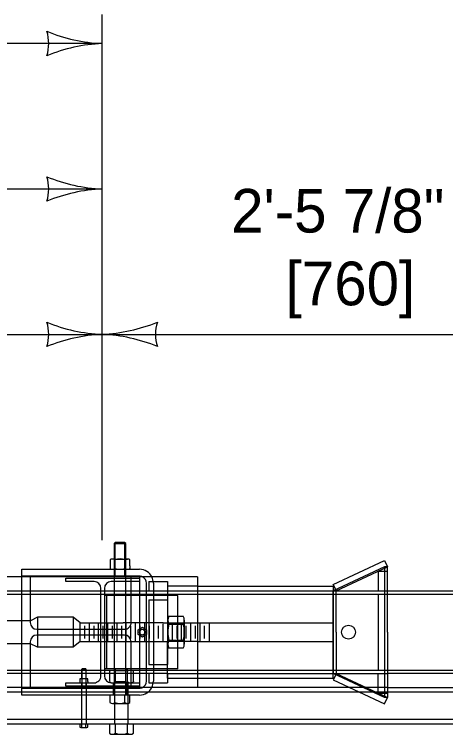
# Model space of a CAD drawing. Extents: x 49991.4 to 50021, y 49987.6 to 50011.4.
# Drawn here: x 50015.632 to 50016.226, y 49997.392 to 49998.382 of the extents above; entities that cross this region are included whole.
import ezdxf

# ---------------------------------------------------------------- set-up
doc = ezdxf.new("R2010")
doc.units = 0
for name, color, linetype in [('Level 1', 7, 'Continuous'), ('Level 2', 7, 'Continuous'), ('Level 3', 7, 'Continuous'), ('Level 4', 7, 'Continuous')]:
    doc.layers.add(name, color=color, linetype=linetype)

msp = doc.modelspace()

# ---------------------------------------------------------------- linework, layer by layer
at = {"layer": 'Level 1'}
for p, q in [((50015.76969, 49997.65453), (50015.77128, 49997.65611)), ((50015.76969, 49997.65453), (50015.77128, 49997.65611)), ((50015.78398, 49997.65611), (50015.77128, 49997.65611)), ((50015.78398, 49997.65611), (50015.77128, 49997.65611)), ((50015.78556, 49997.65453), (50015.78398, 49997.65611)), ((50015.78556, 49997.65453), (50015.78398, 49997.65611)), ((50015.76969, 49997.65453), (50015.76969, 49997.63336)), ((50015.78556, 49997.63336), (50015.78556, 49997.65453)), ((50015.76398, 49997.63241), (50015.76398, 49997.62335)), ((50015.77014, 49997.63336), (50015.76741, 49997.63336)), ((50015.77014, 49997.63336), (50015.78802, 49997.63336)), ((50015.77085, 49997.62014), (50015.77085, 49997.63241)), ((50015.78459, 49997.62014), (50015.78459, 49997.63241)), ((50015.79146, 49997.62411), (50015.79146, 49997.63241)), ((50016.07143, 49997.5983), (50016.14204, 49997.63113)), ((50016.14204, 49997.63113), (50016.14606, 49997.62253)), ((50015.76398, 49997.62335), (50015.76398, 49997.62014)), ((50015.76741, 49997.61919), (50015.78802, 49997.61919)), ((50015.79146, 49997.62411), (50015.79146, 49997.62014)), ((50015.79626, 49997.61919), (50015.8046, 49997.61919)), ((50016.14204, 49997.62253), (50016.07143, 49997.58969)), ((50016.14606, 49997.62253), (50016.14204, 49997.62253)), ((50016.14204, 49997.62253), (50016.14204, 49997.44294)), ((50016.14606, 49997.53273), (50016.14606, 49997.62253)), ((50016.14606, 49997.53273), (50016.14606, 49997.61662)), ((50015.88463, 49997.60868), (50012.22863, 49997.60868)), ((50015.64262, 49997.60969), (50015.64262, 49997.60868)), ((50015.65417, 49997.60868), (50015.65417, 49997.60969)), ((50015.8046, 49997.60969), (50015.79626, 49997.60969)), ((50015.8046, 49997.60969), (50015.8046, 49997.60868)), ((50015.88463, 49997.60868), (50015.88463, 49997.45678)), ((50015.88463, 49997.59602), (50016.07143, 49997.59602)), ((50016.07473, 49997.59123), (50016.07143, 49997.5983)), ((50016.07143, 49997.59602), (50016.07143, 49997.54539)), ((50016.07143, 49997.58969), (50016.07143, 49997.47577)), ((50016.07143, 49997.47577), (50016.07143, 49997.58969)), ((50016.07473, 49997.59123), (50016.07545, 49997.58969)), ((50016.14606, 49997.58972), (50016.35107, 49997.58969)), ((50015.88463, 49997.54539), (50016.07143, 49997.54539)), ((50016.14606, 49997.53273), (50016.14606, 49997.44294)), ((50016.14606, 49997.53273), (50016.14606, 49997.44884)), ((50015.88463, 49997.52007), (50016.07143, 49997.52007)), ((50016.07143, 49997.46944), (50016.07143, 49997.52007)), ((50015.88463, 49997.46944), (50016.07143, 49997.46944)), ((50016.14204, 49997.44294), (50016.07143, 49997.47577)), ((50016.07473, 49997.47423), (50016.07143, 49997.46717)), ((50016.07143, 49997.46717), (50016.14204, 49997.43433)), ((50016.34628, 49997.47577), (50016.14606, 49997.47574)), ((50015.88463, 49997.45678), (50012.22863, 49997.45678)), ((50016.09376, 49997.45678), (50015.40225, 49997.45678)), ((50015.64262, 49997.45678), (50015.64262, 49997.45577)), ((50015.65417, 49997.45678), (50015.65417, 49997.45577)), ((50016.14606, 49997.45678), (50016.34164, 49997.45678)), ((50016.14204, 49997.43433), (50016.14606, 49997.44294)), ((50016.14606, 49997.44294), (50016.14204, 49997.44294)), ((50016.34164, 49997.40615), (50015.40225, 49997.40615)), ((50015.72387, 49997.40154), (50015.73212, 49997.40154)), ((50015.72387, 49997.40154), (50015.73212, 49997.40154)), ((50015.72524, 49997.40198), (50015.72524, 49997.40615)), ((50015.72524, 49997.40198), (50015.72524, 49997.40615)), ((50015.73074, 49997.40198), (50015.73074, 49997.40615)), ((50015.73074, 49997.40198), (50015.73074, 49997.40615)), ((50015.77141, 49997.39365), (50015.77141, 49997.40615)), ((50015.77141, 49997.39365), (50015.77141, 49997.40615)), ((50015.7879, 49997.39365), (50015.7879, 49997.40615)), ((50015.7879, 49997.39365), (50015.7879, 49997.40615)), ((50015.76729, 49997.39233), (50015.79203, 49997.39233)), ((50015.76729, 49997.39233), (50015.79203, 49997.39233))]:
    msp.add_line(p, q, dxfattribs=at)
for points in [[(50015.8046, 49997.60969), (50015.64262, 49997.60969), (50015.64262, 49997.61919), (50015.8046, 49997.61919)], [(50015.73349, 49997.40198), (50015.73349, 49997.40615), (50015.7225, 49997.40615), (50015.7225, 49997.40198)], [(50015.73349, 49997.40198), (50015.73349, 49997.40615), (50015.7225, 49997.40615), (50015.7225, 49997.40198)], [(50015.79615, 49997.39365), (50015.79615, 49997.40615), (50015.76317, 49997.40615), (50015.76317, 49997.39365)], [(50015.79615, 49997.39365), (50015.79615, 49997.40615), (50015.76317, 49997.40615), (50015.76317, 49997.39365)]]:
    msp.add_lwpolyline(points, dxfattribs=at)
msp.add_lwpolyline([(50015.80847, 49997.53958), (50015.81442, 49997.53616), (50015.81442, 49997.52931), (50015.80847, 49997.52588), (50015.80252, 49997.52931), (50015.80252, 49997.53616)], close=True, dxfattribs=at)
for centre, major_axis, start_param, end_param in [((50015.76741, 49997.62671), (-0.00667, 0), 4.291765, 5.25309), ((50015.76741, 49997.62671), (-0.00667, 0), 4.171688, 4.291765), ((50015.77772, 49997.60817), (-0.02527, 0), 4.437007, 4.987771), ((50015.78803, 49997.62671), (-0.00667, 0), 4.538561, 5.25309), ((50015.78803, 49997.62671), (-0.00667, 0), 4.171687, 4.538561), ((50015.76741, 49997.62584), (-0.00667, 0), 1.030095, 2.111498), ((50015.77772, 49997.64438), (-0.02527, 0), 1.295415, 1.84618), ((50015.78803, 49997.62584), (-0.00667, 0), 1.030095, 2.111498), ((50015.8046, 49997.6002), (-0.01904, 0), 3.604629, 4.712389), ((50015.8046, 49997.6002), (-0.00952, 0), 4.246301, 4.712389), ((50015.80847, 49997.53273), (-0.00353, 0), 5.020149, 5.195336), ((50015.80847, 49997.53273), (-0.00353, 0), 5.020149, 5.195336), ((50015.80847, 49997.53273), (-0.00353, 0), 4.455169, 4.688481), ((50015.80847, 49997.53273), (-0.00353, 0), 4.455169, 4.688481), ((50015.80847, 49997.53273), (-0.00353, 0), 4.455169, 4.688481), ((50015.80847, 49997.53273), (-0.00353, 0), 4.455169, 4.688481), ((50015.80847, 49997.53273), (-0.00353, 0), 0.050953, 0.393038), ((50015.80847, 49997.53273), (-0.00353, 0), 0.050953, 0.393038), ((50015.80847, 49997.53273), (-0.00353, 0), 5.563044, 5.953877), ((50015.80847, 49997.53273), (-0.00353, 0), 5.563044, 5.953877), ((50015.80847, 49997.53273), (-0.00353, 0), 0.642388, 1.07769), ((50015.80847, 49997.53273), (-0.00353, 0), 0.642388, 1.07769), ((50015.80847, 49997.53273), (-0.00353, 0), 1.524027, 1.964776), ((50015.80847, 49997.53273), (-0.00353, 0), 3.688317, 4.066094), ((50015.80847, 49997.53273), (-0.00353, 0), 3.688317, 4.066094), ((50015.80847, 49997.53273), (-0.00353, 0), 3.688317, 4.066094), ((50015.80847, 49997.53273), (-0.00353, 0), 3.688317, 4.066094), ((50015.80847, 49997.53273), (-0.00353, 0), 2.328597, 2.659517), ((50015.80847, 49997.53273), (-0.00353, 0), 2.328597, 2.659517), ((50015.80847, 49997.53273), (-0.00353, 0), 2.328597, 2.659517), ((50015.80847, 49997.53273), (-0.00353, 0), 2.328597, 2.659517), ((50015.80847, 49997.53273), (-0.00353, 0), 3.003616, 3.367487), ((50015.80847, 49997.53273), (-0.00353, 0), 3.003616, 3.367487), ((50015.80847, 49997.53273), (-0.00353, 0), 3.003616, 3.367487), ((50015.80847, 49997.53273), (-0.00353, 0), 3.003616, 3.367487), ((50015.72387, 49997.40388), (-0.00235, 0), 0.945365, 2.196228), ((50015.72387, 49997.40388), (-0.00235, 0), 0.945365, 2.196228), ((50015.72799, 49997.41024), (-0.00872, 0), 1.250246, 1.891347), ((50015.72799, 49997.41024), (-0.00872, 0), 1.250246, 1.891347), ((50015.73212, 49997.40388), (-0.00235, 0), 0.945366, 2.196226), ((50015.73212, 49997.40388), (-0.00235, 0), 0.945366, 2.196226), ((50015.76729, 49997.39935), (-0.00704, 0), 0.945365, 2.196228), ((50015.76729, 49997.39935), (-0.00704, 0), 0.945365, 2.196228), ((50015.77966, 49997.41842), (-0.02617, 0), 1.250246, 1.891347), ((50015.77966, 49997.41842), (-0.02617, 0), 1.250246, 1.891347), ((50015.79203, 49997.39935), (-0.00704, 0), 0.945366, 2.196226), ((50015.79203, 49997.39935), (-0.00704, 0), 0.945366, 2.196226)]:
    msp.add_ellipse(centre, major_axis=major_axis, ratio=0.99715, start_param=start_param, end_param=end_param, dxfattribs=at)
msp.add_ellipse((50015.80847, 49997.53273), major_axis=(-0.00397, 0), ratio=0.99715, dxfattribs=at)
msp.add_ellipse((50015.80847, 49997.53273), major_axis=(-0.00397, 0), ratio=0.99715, dxfattribs=at)
at = {"layer": 'Level 3'}
for p, q in [((50015.7531, 49997.65919), (50015.7531, 49998.3823)), ((50015.7531, 49998.34228), (50001.2124, 49998.34228)), ((50012.22863, 49998.14228), (50015.7531, 49998.14228)), ((50013.1585, 49997.94228), (50015.7531, 49997.94228)), ((50015.7531, 49997.94228), (50016.49863, 49997.94228))]:
    msp.add_line(p, q, dxfattribs=at)
for centre, radius, start, end in [((50015.76226, 49998.56441), 0.22232, 247.45601, 267.63952), ((50015.62489, 49998.34228), 0.05477, 342.13882, 17.86118), ((50015.76459, 49998.10957), 0.233, 92.82731, 112.07716), ((50015.76226, 49998.36441), 0.22232, 247.45601, 267.63952), ((50015.62489, 49998.14228), 0.05477, 342.13882, 17.86118), ((50015.76459, 49997.90957), 0.233, 92.82731, 112.07716), ((50015.76226, 49998.16441), 0.22232, 247.45601, 267.63952), ((50015.62489, 49997.94228), 0.05477, 342.13882, 17.86118), ((50015.74161, 49998.17499), 0.233, 272.82731, 292.07716), ((50015.88131, 49997.94228), 0.05477, 162.13882, 197.86118), ((50015.76459, 49997.70957), 0.233, 92.82731, 112.07716), ((50015.74394, 49997.72015), 0.22232, 67.45601, 87.63952)]:
    msp.add_arc(centre, radius, start, end, dxfattribs=at)
at = {"layer": 'Level 4'}
for p, q in [((50015.76969, 49997.65453), (50015.78556, 49997.65453)), ((50015.76969, 49997.65453), (50015.78556, 49997.65453)), ((50015.77128, 49997.60864), (50015.77128, 49997.65453)), ((50015.78398, 49997.65453), (50015.78398, 49997.60864)), ((50015.76969, 49997.63336), (50015.76969, 49997.44627)), ((50015.78556, 49997.44627), (50015.78556, 49997.63336)), ((50016.07545, 49997.58969), (50016.14606, 49997.62253)), ((50016.13337, 49997.61662), (50016.14606, 49997.61662)), ((50016.13337, 49997.61662), (50016.13337, 49997.58972)), ((50015.81412, 49997.46526), (50015.81412, 49997.6002)), ((50015.81754, 49997.60235), (50015.81754, 49997.58969)), ((50015.81754, 49997.60235), (50015.84293, 49997.60235)), ((50015.82365, 49997.6002), (50015.82365, 49997.46526)), ((50015.84293, 49997.60235), (50015.84293, 49997.58969)), ((50015.88463, 49997.59602), (50015.84293, 49997.59602)), ((50015.84293, 49997.59602), (50015.84293, 49997.54539)), ((50015.31803, 49997.58969), (50015.84293, 49997.58969)), ((50015.75144, 49997.4726), (50015.75144, 49997.59286)), ((50015.7562, 49997.59286), (50015.7562, 49997.4726)), ((50015.84293, 49997.58969), (50016.07143, 49997.58969)), ((50016.07143, 49997.58969), (50016.14606, 49997.58969)), ((50016.07545, 49997.53273), (50016.07545, 49997.58969)), ((50015.27995, 49997.58495), (50016.34934, 49997.58495)), ((50015.85754, 49997.58336), (50015.7562, 49997.58336)), ((50015.7594, 49997.4821), (50015.7594, 49997.58336)), ((50015.81754, 49997.57703), (50015.84293, 49997.57703)), ((50015.81754, 49997.57703), (50015.81754, 49997.48843)), ((50015.84293, 49997.57703), (50015.84293, 49997.48843)), ((50015.85754, 49997.4821), (50015.85754, 49997.58336)), ((50016.13337, 49997.58495), (50016.13337, 49997.48052)), ((50015.65468, 49997.54855), (50015.52139, 49997.54855)), ((50015.6642, 49997.5533), (50015.65468, 49997.54855)), ((50015.71339, 49997.5533), (50015.6642, 49997.5533)), ((50015.6642, 49997.5533), (50015.6642, 49997.51216)), ((50015.72291, 49997.54539), (50015.71339, 49997.5533)), ((50015.71339, 49997.5533), (50015.71339, 49997.51216)), ((50015.84351, 49997.51643), (50015.84351, 49997.54932)), ((50015.84503, 49997.5548), (50015.86473, 49997.5548)), ((50015.86626, 49997.54932), (50015.86626, 49997.51643)), ((50015.66325, 49997.53678), (50015.78398, 49997.53678)), ((50015.72291, 49997.54539), (50015.78209, 49997.54539)), ((50015.72291, 49997.52007), (50015.72291, 49997.54539)), ((50015.72926, 49997.52387), (50015.72926, 49997.54159)), ((50015.73561, 49997.52007), (50015.73561, 49997.54539)), ((50015.74195, 49997.52387), (50015.74195, 49997.54159)), ((50015.7483, 49997.52007), (50015.7483, 49997.54539)), ((50015.75465, 49997.52387), (50015.75465, 49997.54159)), ((50015.761, 49997.52007), (50015.761, 49997.54539)), ((50015.76734, 49997.52387), (50015.76734, 49997.54159)), ((50015.77369, 49997.52007), (50015.77369, 49997.54539)), ((50015.78004, 49997.52387), (50015.78004, 49997.54159)), ((50015.83716, 49997.54539), (50015.78209, 49997.54539)), ((50015.78638, 49997.53905), (50015.78638, 49997.54539)), ((50015.78638, 49997.52007), (50015.78638, 49997.53905)), ((50015.79273, 49997.52968), (50015.79273, 49997.54159)), ((50015.79908, 49997.52007), (50015.79908, 49997.54539)), ((50015.80543, 49997.52387), (50015.80543, 49997.54159)), ((50015.81177, 49997.52007), (50015.81177, 49997.54539)), ((50015.81812, 49997.52387), (50015.81812, 49997.54159)), ((50015.82447, 49997.52007), (50015.82447, 49997.54539)), ((50015.83082, 49997.52387), (50015.83082, 49997.54159)), ((50015.83716, 49997.52007), (50015.83716, 49997.54417)), ((50015.8374, 49997.54539), (50015.84351, 49997.54539)), ((50015.84293, 49997.54539), (50015.88463, 49997.54539)), ((50015.84503, 49997.54384), (50015.86473, 49997.54384)), ((50015.84986, 49997.52007), (50015.84986, 49997.54539)), ((50015.8562, 49997.52387), (50015.8562, 49997.54159)), ((50015.86255, 49997.52007), (50015.86255, 49997.54539)), ((50015.8689, 49997.52387), (50015.8689, 49997.54159)), ((50015.87525, 49997.52007), (50015.87525, 49997.54539)), ((50015.88159, 49997.52387), (50015.88159, 49997.54159)), ((50015.88794, 49997.52007), (50015.88794, 49997.54539)), ((50015.89429, 49997.52387), (50015.89429, 49997.54159)), ((50015.90063, 49997.54539), (50015.90063, 49997.52007)), ((50015.78398, 49997.52868), (50015.66325, 49997.52868)), ((50015.79273, 49997.52387), (50015.79273, 49997.52968)), ((50016.07545, 49997.53273), (50016.07545, 49997.47577)), ((50015.65468, 49997.51691), (50015.52139, 49997.51691)), ((50015.6642, 49997.51216), (50015.65468, 49997.51691)), ((50015.72291, 49997.52007), (50015.71339, 49997.51216)), ((50015.72291, 49997.52007), (50015.79924, 49997.52007)), ((50015.79908, 49997.52007), (50015.83248, 49997.52007)), ((50015.83248, 49997.52007), (50015.84351, 49997.52007)), ((50015.88463, 49997.52007), (50015.84293, 49997.52007)), ((50015.84293, 49997.46944), (50015.84293, 49997.52007)), ((50015.88463, 49997.52007), (50015.84293, 49997.52007)), ((50015.84503, 49997.52192), (50015.86473, 49997.52192)), ((50015.71339, 49997.51216), (50015.6642, 49997.51216)), ((50015.86473, 49997.51095), (50015.84503, 49997.51095)), ((50015.81754, 49997.48843), (50015.84293, 49997.48843)), ((50015.27995, 49997.48052), (50016.34934, 49997.48052)), ((50015.72482, 49997.48146), (50015.72545, 49997.4821)), ((50015.72482, 49997.48146), (50015.72545, 49997.4821)), ((50015.72482, 49997.48146), (50015.73117, 49997.48146)), ((50015.72482, 49997.48146), (50015.73117, 49997.48146)), ((50015.72482, 49997.48146), (50015.72482, 49997.46878)), ((50015.73053, 49997.4821), (50015.72545, 49997.4821)), ((50015.73053, 49997.4821), (50015.72545, 49997.4821)), ((50015.72545, 49997.45552), (50015.72545, 49997.48146)), ((50015.73117, 49997.48146), (50015.73053, 49997.4821)), ((50015.73117, 49997.48146), (50015.73053, 49997.4821)), ((50015.73053, 49997.48146), (50015.73053, 49997.45552)), ((50015.73117, 49997.46878), (50015.73117, 49997.48146)), ((50015.85754, 49997.4821), (50015.7562, 49997.4821)), ((50015.76328, 49997.47898), (50015.76328, 49997.46469)), ((50015.79214, 49997.48012), (50015.7674, 49997.48012)), ((50015.77014, 49997.4802), (50015.77204, 49997.4821)), ((50015.77014, 49997.4802), (50015.77204, 49997.4821)), ((50015.77014, 49997.4802), (50015.77014, 49997.48012)), ((50015.77014, 49997.4802), (50015.78918, 49997.4802)), ((50015.77152, 49997.46465), (50015.77152, 49997.47898)), ((50015.78728, 49997.4821), (50015.77204, 49997.4821)), ((50015.78918, 49997.4802), (50015.78728, 49997.4821)), ((50015.78918, 49997.4802), (50015.78728, 49997.4821)), ((50015.78801, 49997.46469), (50015.78801, 49997.47898)), ((50015.78918, 49997.48012), (50015.78918, 49997.4802)), ((50015.79626, 49997.46469), (50015.79626, 49997.47898)), ((50015.84293, 49997.47577), (50015.31803, 49997.47577)), ((50015.7225, 49997.4684), (50015.7225, 49997.46469)), ((50015.73212, 49997.46878), (50015.72387, 49997.46878)), ((50015.72524, 49997.4684), (50015.72524, 49997.46469)), ((50015.73074, 49997.4684), (50015.73074, 49997.46469)), ((50015.73349, 49997.46469), (50015.73349, 49997.4684)), ((50015.81754, 49997.47577), (50015.81754, 49997.46311)), ((50015.84293, 49997.47577), (50016.07143, 49997.47577)), ((50015.84293, 49997.47577), (50015.84293, 49997.46311)), ((50015.84293, 49997.46944), (50015.88463, 49997.46944)), ((50016.07143, 49997.47577), (50016.14606, 49997.47577)), ((50016.07545, 49997.47577), (50016.14606, 49997.44294)), ((50016.13337, 49997.44884), (50016.13337, 49997.47574)), ((50015.7225, 49997.46469), (50015.7225, 49997.46349)), ((50015.72387, 49997.46311), (50015.73212, 49997.46311)), ((50015.72482, 49997.46328), (50015.72482, 49997.40615)), ((50015.72524, 49997.46469), (50015.72524, 49997.46349)), ((50015.72524, 49997.46349), (50015.72524, 49997.46349)), ((50015.73074, 49997.46469), (50015.73074, 49997.46349)), ((50015.73117, 49997.46328), (50015.73117, 49997.40615)), ((50015.73349, 49997.46469), (50015.73349, 49997.46349)), ((50015.7674, 49997.46311), (50015.79214, 49997.46311)), ((50015.76811, 49997.46311), (50015.76811, 49997.45836)), ((50015.76811, 49997.46311), (50015.76811, 49997.45836)), ((50015.78556, 49997.46465), (50015.76969, 49997.46465)), ((50015.78556, 49997.46465), (50015.76969, 49997.46465)), ((50015.78556, 49997.46465), (50015.76969, 49997.46465)), ((50015.78556, 49997.46465), (50015.76969, 49997.46465)), ((50015.77014, 49997.46311), (50015.77014, 49997.40615)), ((50015.77152, 49997.46469), (50015.77152, 49997.46425)), ((50015.78715, 49997.45836), (50015.78715, 49997.46311)), ((50015.78715, 49997.45836), (50015.78715, 49997.46311)), ((50015.78801, 49997.46469), (50015.78801, 49997.46425)), ((50015.78918, 49997.40615), (50015.78918, 49997.46311)), ((50015.79305, 49997.45678), (50015.79305, 49997.45577)), ((50015.79626, 49997.46469), (50015.79626, 49997.46425)), ((50015.8046, 49997.45678), (50015.8046, 49997.45577)), ((50015.81754, 49997.46311), (50015.84293, 49997.46311)), ((50016.14606, 49997.45678), (50016.09376, 49997.45678)), ((50016.34164, 49997.45045), (50015.45302, 49997.45045)), ((50015.73117, 49997.45552), (50015.72482, 49997.45552)), ((50015.73117, 49997.45552), (50015.72482, 49997.45552)), ((50015.76811, 49997.45577), (50015.76811, 49997.44627)), ((50015.76811, 49997.45577), (50015.76811, 49997.44627)), ((50015.78715, 49997.44627), (50015.78715, 49997.45577)), ((50015.78715, 49997.44627), (50015.78715, 49997.45577)), ((50016.13337, 49997.44884), (50016.14606, 49997.44884)), ((50015.77076, 49997.43586), (50015.77076, 49997.44627)), ((50015.77076, 49997.43586), (50015.77076, 49997.44627)), ((50015.7845, 49997.43586), (50015.7845, 49997.44627)), ((50015.7845, 49997.43586), (50015.7845, 49997.44627)), ((50015.76732, 49997.43476), (50015.78793, 49997.43476)), ((50015.76732, 49997.43476), (50015.78793, 49997.43476)), ((50016.34164, 49997.41248), (50015.45302, 49997.41248))]:
    msp.add_line(p, q, dxfattribs=at)
for points in [[(50015.64262, 49997.60969), (50015.65417, 49997.60969), (50015.65417, 49997.54583)], [(50015.65417, 49997.51963), (50015.65417, 49997.45577), (50015.64262, 49997.45577), (50015.64262, 49997.60969)], [(50015.74192, 49997.60235), (50015.70305, 49997.60235), (50015.70305, 49997.6071), (50015.8046, 49997.6071), (50015.8046, 49997.60235), (50015.76573, 49997.60235)], [(50015.79305, 49997.54583), (50015.79305, 49997.60969), (50015.8046, 49997.60969), (50015.8046, 49997.45577), (50015.79305, 49997.45577), (50015.79305, 49997.51963)], [(50015.70305, 49997.45836), (50015.70305, 49997.46311), (50015.74192, 49997.46311)], [(50015.76573, 49997.46311), (50015.8046, 49997.46311), (50015.8046, 49997.45836), (50015.70305, 49997.45836)], [(50015.8046, 49997.44627), (50015.64262, 49997.44627), (50015.64262, 49997.45577), (50015.8046, 49997.45577)], [(50015.79137, 49997.43586), (50015.79137, 49997.44627), (50015.76389, 49997.44627), (50015.76389, 49997.43586)], [(50015.79137, 49997.43586), (50015.79137, 49997.44627), (50015.76389, 49997.44627), (50015.76389, 49997.43586)]]:
    msp.add_lwpolyline(points, dxfattribs=at)
for centre, major_axis, start_param, end_param in [((50015.8046, 49997.6002), (-0.00952, 0), 3.141593, 4.246301), ((50015.8046, 49997.6002), (-0.01904, 0), 3.141593, 3.604629), ((50015.74192, 49997.59286), (-0.00952, 0), 3.141593, 4.712389), ((50015.76573, 49997.59286), (-0.00952, 0), 4.712389, 6.283185), ((50015.66325, 49997.54583), (-0.00908, 0), 0, 1.570796), ((50015.78398, 49997.54583), (-0.00908, 0), 1.570796, 3.141593), ((50015.85419, 49997.54932), (-0.01068, 0), 5.742484, 6.823887), ((50015.85558, 49997.54932), (-0.01068, 0), 2.600892, 3.682294), ((50015.88394, 49997.53288), (-0.04043, 0), 6.007802, 6.558567), ((50015.82583, 49997.53288), (-0.04043, 0), 2.866211, 3.416975), ((50015.66325, 49997.51963), (-0.00908, 0), 4.712389, 6.283185), ((50015.78398, 49997.51963), (-0.00908, 0), 3.141593, 4.712389), ((50015.85419, 49997.51643), (-0.01068, 0), 5.742484, 6.823887), ((50015.85558, 49997.51643), (-0.01068, 0), 2.600892, 3.682294), ((50015.7674, 49997.47214), (-0.00801, 0), 4.171688, 5.25309), ((50015.77977, 49997.44989), (-0.03032, 0), 4.437007, 4.987771), ((50015.79214, 49997.47214), (-0.00801, 0), 4.171687, 5.25309), ((50015.72387, 49997.46612), (-0.00267, 0), 4.171688, 5.25309), ((50015.72799, 49997.4587), (-0.01011, 0), 4.437007, 4.987772), ((50015.73212, 49997.46612), (-0.00267, 0), 4.171688, 5.25309), ((50015.74192, 49997.4726), (-0.00952, 0), 1.570796, 3.141593), ((50015.76573, 49997.4726), (-0.00952, 0), 0, 1.570796), ((50015.72387, 49997.46577), (-0.00267, 0), 1.030095, 2.111498), ((50015.72799, 49997.47319), (-0.01011, 0), 1.295414, 1.846178), ((50015.73212, 49997.46577), (-0.00267, 0), 1.030095, 2.111498), ((50015.7674, 49997.4711), (-0.00801, 0), 1.030095, 2.111498), ((50015.77977, 49997.49335), (-0.03032, 0), 1.295415, 1.84618), ((50015.79214, 49997.4711), (-0.00801, 0), 1.030095, 2.111498), ((50015.8046, 49997.46526), (-0.01904, 0), 1.570796, 2.678556), ((50015.8046, 49997.46526), (-0.00952, 0), 1.570796, 2.036884), ((50015.8046, 49997.46526), (-0.00952, 0), 2.036884, 3.141593), ((50015.8046, 49997.46526), (-0.01904, 0), 2.678556, 3.141593), ((50015.76732, 49997.44061), (-0.00587, 0), 0.945365, 2.196228), ((50015.76732, 49997.44061), (-0.00587, 0), 0.945365, 2.196228), ((50015.77763, 49997.4565), (-0.02181, 0), 1.250246, 1.891347), ((50015.77763, 49997.4565), (-0.02181, 0), 1.250246, 1.891347), ((50015.78793, 49997.44061), (-0.00587, 0), 0.945366, 2.196226), ((50015.78793, 49997.44061), (-0.00587, 0), 0.945366, 2.196226)]:
    msp.add_ellipse(centre, major_axis=major_axis, ratio=0.99715, start_param=start_param, end_param=end_param, dxfattribs=at)
msp.add_ellipse((50016.09239, 49997.53273), major_axis=(-0.00952, 0), ratio=0.99715, dxfattribs=at)

# ---------------------------------------------------------------- texts
at = {"layer": 'Level 2'}
for s, p in [('2\'-5 7/8"', (50015.93079, 49998.08228)), ('[760]', (50016.00577, 49997.98228))]:
    msp.add_text(s, height=0.06, dxfattribs=at).set_placement(p)

doc.saveas('drawing.dxf')
